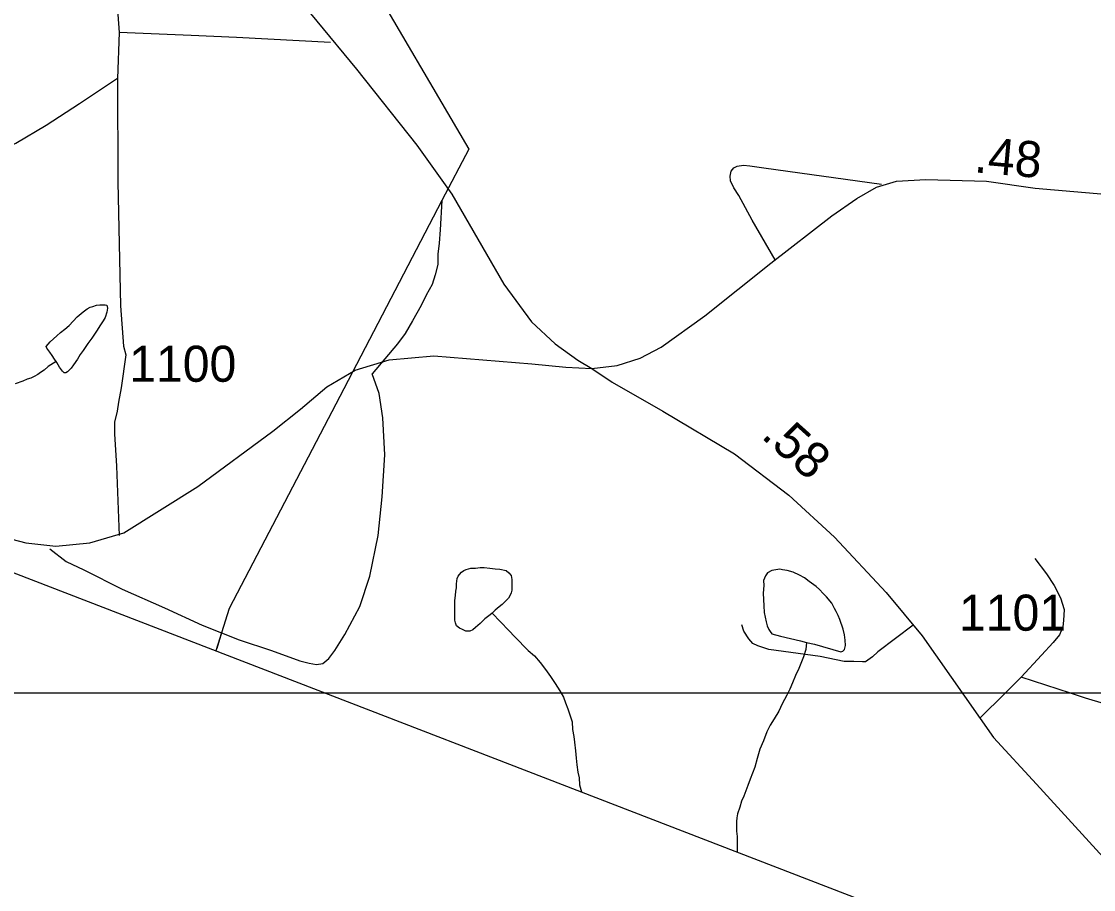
# Model space of a CAD drawing. Extents: x 2001466 to 2224147, y 644118 to 847247.
# Drawn here: x 2048097 to 2051817, y 657493 to 660503 of the extents above; entities that cross this region are included whole.
import ezdxf

# ---------------------------------------------------------------- set-up
doc = ezdxf.new("R2010")
doc.units = 0
for name, color, linetype in [('Exist Boundary Political CountyLine', 7, 'Continuous'), ('Exist Hydrographic Misc Water Feature', 7, 'Continuous'), ('Exist Road Non-System Type 51', 7, 'Continuous'), ('Exist Road Secondary Mileage Hundredths English Label', 7, 'Continuous'), ('Exist Road Secondary Type 51 Attributed', 7, 'Continuous'), ('Exist Road Secondary Type 51 Number Label', 7, 'Continuous'), ('Exist Utilities Electrical Transmission Line', 7, 'Continuous'), ('Map Preparation Inset Cut Line', 7, 'Continuous')]:
    doc.layers.add(name, color=color, linetype=linetype)

msp = doc.modelspace()

# ---------------------------------------------------------------- linework, layer by layer
at = {"layer": 'Exist Boundary Political CountyLine'}
msp.add_lwpolyline([(2025347, 667357.1), (2026293.9, 666990.5), (2073692.9, 648709.4), (2076162.7, 647794.5), (2078580.1, 646988.2), (2083338.8, 645254.9), (2086621.1, 644117.9)], dxfattribs=at)
at = {"layer": 'Exist Hydrographic Misc Water Feature'}
for points in [[(2048217.7, 659324.5), (2048211.7, 659332.5), (2048203.7, 659344.4), (2048195.5, 659356.4), (2048185.7, 659370.4), (2048183.6, 659376.4), (2048189.6, 659384.4), (2048197.6, 659392.4), (2048219.7, 659412.5), (2048233.5, 659424.5), (2048247.4, 659436.5), (2048263.4, 659448.5), (2048291.3, 659478.6), (2048311.4, 659496.6), (2048325.3, 659506.6), (2048335.4, 659512.7), (2048345.4, 659514.7), (2048357.3, 659518.7), (2048369.4, 659520.7), (2048381.3, 659520.7), (2048387.5, 659520.7), (2048393.4, 659518.7), (2048395.5, 659508.8), (2048393.4, 659494.8), (2048387.5, 659476.7), (2048381.3, 659464.7), (2048371.5, 659450.7), (2048357.5, 659428.7), (2048341.5, 659404.6), (2048327.6, 659386.7), (2048311.6, 659362.6), (2048301.6, 659348.6), (2048291.7, 659332.6), (2048277.8, 659312.6), (2048269.8, 659300.5), (2048257.7, 659288.5), (2048251.7, 659284.5), (2048245.8, 659284.5), (2048239.8, 659290.5), (2048229.8, 659304.5), (2048219.7, 659320.5), (2048217.7, 659324.5)], [(2048217.7, 659324.5), (2048189.8, 659306.4), (2048175.9, 659294.4), (2048163.8, 659286.3), (2048153.9, 659278.3), (2048141.8, 659272.3), (2048129.9, 659266.3), (2048117.8, 659262.3), (2048101.8, 659256.3), (2048075.8, 659246.2)], [(2049731.2, 658451.5), (2049723.2, 658445.5), (2049705.1, 658431.4), (2049689.1, 658415.4), (2049673.1, 658401.4), (2049663.3, 658393.4), (2049653.3, 658389.3), (2049639.3, 658389.3), (2049627.2, 658395.2), (2049617.2, 658399.2), (2049607.1, 658407.3), (2049603, 658417.3), (2049601.2, 658427.3), (2049601.2, 658439.3), (2049601.2, 658451.3), (2049601.2, 658459.3), (2049601, 658473.2), (2049601, 658495.2), (2049603, 658513.2), (2049605.1, 658527.2), (2049606.9, 658539.2), (2049606.9, 658553.2), (2049608.8, 658571.2), (2049612.9, 658579.2), (2049616.8, 658585.3), (2049624.8, 658593.3), (2049632.8, 658599.3), (2049640.7, 658603.2), (2049656.7, 658607.3), (2049672.7, 658607.3), (2049688.7, 658609.3), (2049702.7, 658609.3), (2049722.8, 658607.5), (2049740.8, 658605.5), (2049756.8, 658603.5), (2049778.7, 658599.5), (2049788.8, 658591.6), (2049796.8, 658581.6), (2049798.8, 658567.6), (2049798.8, 658551.6), (2049798.8, 658541.6), (2049798.8, 658531.6), (2049796.8, 658521.6), (2049792.9, 658513.5), (2049787, 658503.5), (2049776.9, 658493.5), (2049765, 658481.5), (2049755, 658473.5), (2049741, 658461.5), (2049731.2, 658451.5)], [(2050821, 658349.5), (2050848.9, 658343.6), (2050941, 658317.8), (2050947.1, 658319.8), (2050953.1, 658325.8), (2050957, 658339.8), (2050954.9, 658357.8), (2050952.9, 658375.8), (2050949, 658395.8), (2050936.9, 658429.7), (2050930.9, 658443.7), (2050924.8, 658457.7), (2050918.8, 658467.7), (2050908.8, 658485.7), (2050890.7, 658507.6), (2050882.8, 658515.6), (2050878.6, 658519.6), (2050866.8, 658533.6), (2050854.7, 658543.6), (2050830.7, 658561.5), (2050814.7, 658573.5), (2050796.6, 658583.5), (2050774.7, 658593.4), (2050754.6, 658599.4), (2050738.6, 658601.4), (2050728.6, 658603.4), (2050714.6, 658601.3), (2050700.7, 658599.3), (2050686.5, 658591.2), (2050678.5, 658581.2), (2050672.6, 658565.2), (2050672.8, 658547.2), (2050670.7, 658521.2), (2050672.8, 658477.2), (2050674.8, 658453.2), (2050681, 658421.3), (2050684.9, 658407.3), (2050691, 658395.3), (2050694.9, 658387.3), (2050700.9, 658379.3), (2050731, 658371.3), (2050800.9, 658355.5), (2050821, 658349.5)], [(2049731.2, 658451.5), (2049789, 658391.6), (2049809.3, 658369.6), (2049855.2, 658321.7), (2049877.4, 658303.8), (2049897.3, 658279.8), (2049915.3, 658255.8), (2049933.6, 658231.9), (2049949.6, 658208), (2049965.6, 658182), (2049977.7, 658160), (2049985.6, 658140), (2049993.6, 658120), (2049997.5, 658106), (2050007.8, 658074.1), (2050009.6, 658048.1), (2050013.7, 658024.1), (2050015.8, 658004.1), (2050019.9, 657974), (2050021.9, 657948.1), (2050024, 657926.1), (2050027.9, 657900.1), (2050032, 657880.1), (2050034, 657856.1), (2050038.1, 657840.1), (2050041, 657831.6)], [(2050821, 658349.5), (2050819.2, 658325.5), (2050811, 658299.5), (2050795.2, 658259.5), (2050783.3, 658235.5), (2050773.3, 658209.4), (2050763.4, 658187.5), (2050753.4, 658167.5), (2050737.4, 658137.4), (2050725.5, 658111.4), (2050709.5, 658085.4), (2050695.5, 658063.3), (2050683.6, 658039.4), (2050671.8, 658009.3), (2050659.7, 657979.3), (2050649.8, 657947.3), (2050641.8, 657917.3), (2050626, 657875.3), (2050618, 657853.3), (2050604.1, 657817.2), (2050596.1, 657799.2), (2050590.1, 657779.2), (2050582.1, 657755.2), (2050580.1, 657741.2), (2050578.2, 657729.2), (2050578.2, 657715.2), (2050578.2, 657695.2), (2050580.3, 657677.2), (2050580.3, 657649.2), (2050580.3, 657635.2), (2050580.4, 657623.6)]]:
    msp.add_lwpolyline(points, dxfattribs=at)
at = {"layer": 'Exist Road Non-System Type 51'}
for p, q in [((2048436.2, 660465), (2048431, 660305.1)), ((2051566.7, 658229.5), (2051510.2, 658173.9)), ((2051737.3, 658173.9), (2051566.7, 658229.5)), ((2051510.2, 658173.9), (2051422.7, 658087.7))]:
    msp.add_line(p, q, dxfattribs=at)
for points in [[(2048921.6, 660731.2), (2048505.6, 660731.6), (2048483.6, 660732.1), (2048467.7, 660734.4), (2048455.7, 660732.6), (2048443.6, 660730.9), (2048435.4, 660719.1), (2048428.9, 660697.2), (2048424.5, 660677.3), (2048423.7, 660637.3), (2048436.2, 660465)], [(2049169.5, 660430.1), (2048843.8, 660446.8), (2048686, 660454), (2048436.2, 660465)], [(2048431, 660305.1), (2048299.2, 660217.8), (2048183.6, 660142.2), (2048078.4, 660080.3), (2047999.8, 660049.9), (2047938.9, 660009.1), (2047874.2, 659974.4), (2047805.6, 659941.8), (2047741.1, 659919.1), (2047698.6, 659896)], [(2048431, 660305.1), (2048431.7, 659947.1), (2048440.9, 659516.9), (2048452.1, 659376.7), (2048459.4, 659346.6), (2048443.1, 659232.9), (2048434.1, 659183.1), (2048429.5, 659151.2), (2048420.7, 659113.3), (2048419.9, 659073.4), (2048427.6, 658961.2), (2048436.7, 658721)], [(2050712.4, 659676.4), (2050633, 659814.4), (2050586.7, 659899.4), (2050569.2, 659925.7), (2050557.7, 659950), (2050556, 659966), (2050560.4, 659983.9), (2050568.7, 659995.7), (2050580.8, 660001.5), (2050602.8, 660005), (2050624.8, 660002.6), (2050672.7, 659995.6), (2051081.8, 659938.8)], [(2049556.4, 659882.3), (2049550.3, 659780.4), (2049547.3, 659734.5), (2049542.6, 659696.6), (2049541.8, 659660.6), (2049533.1, 659624.8), (2049522.4, 659591), (2049501.6, 659553.4), (2049484.9, 659517.7), (2049453.8, 659464.4), (2049429, 659420.9), (2049402.2, 659385.4), (2049314.1, 659281.2)], [(2048791.7, 658382.8), (2048853.3, 658358.6), (2048964.6, 658322.3), (2049063.9, 658286.3), (2049095.7, 658277.6), (2049121.6, 658273.1), (2049143.7, 658276.7), (2049164, 658294.2), (2049184.6, 658321.8), (2049219.7, 658377.1), (2049271.7, 658474.1), (2049305.8, 658579.4), (2049334.7, 658720.8), (2049349.4, 658854.5), (2049358.4, 659000.3), (2049351, 659128.5), (2049338.7, 659212.7), (2049314.1, 659281.2)], [(2048195.7, 658673.9), (2048252.9, 658630.7), (2048314.3, 658601.5), (2048446.9, 658534.8), (2048593.6, 658469.8), (2048724.4, 658409.2), (2048791.7, 658382.8)], [(2051613.1, 658640.5), (2051654, 658587.7), (2051681.2, 658547.1), (2051702.3, 658504.7), (2051715.5, 658464.4), (2051712.7, 658426.5), (2051710.3, 658404.5), (2051699.7, 658376.8), (2051677.1, 658349.2), (2051636.3, 658306), (2051566.7, 658229.5)], [(2051191.1, 658410), (2051068.5, 658317.6), (2051050.1, 658299.9), (2051025.8, 658282.4), (2051015.8, 658282.6), (2050985.8, 658283.3), (2050951.8, 658283.9), (2050868.2, 658301.6), (2050690.6, 658325.2), (2050652.9, 658338), (2050635.1, 658346.4), (2050621.4, 658362.7), (2050603.9, 658389), (2050596.4, 658411.2)], [(2052440, 658089.7), (2052417.9, 658090.2), (2052387.6, 658078.8), (2052357.2, 658057.4), (2052344.9, 658041.7), (2052310.7, 658032.4), (2052296.4, 658020.6), (2052268.4, 658019.2), (2052230.6, 658030), (2052095.3, 658062.7), (2051932.3, 658114), (2051789.2, 658156.9), (2051737.3, 658173.9)]]:
    msp.add_lwpolyline(points, dxfattribs=at)
at = {"layer": 'Exist Road Secondary Type 51 Attributed'}
for points in [[(2047317.1, 662412), (2047529.3, 662218.6), (2048014.4, 661781.3), (2048220.7, 661592.2), (2048349.5, 661460.1), (2048474, 661313.3), (2048683.6, 661045), (2048847.2, 660838), (2049259.4, 660337.3), (2049468.9, 660074.3), (2049591.3, 659904.2), (2049771.3, 659592.6), (2049867.4, 659461.6), (2049949.2, 659385.6), (2050028.3, 659328.5), (2050076.9, 659300)], [(2050076.9, 659300), (2050164.5, 659309.5), (2050244.7, 659335.9), (2050317.6, 659374), (2050468.5, 659481.7), (2050697, 659664.4), (2050909.2, 659829.2), (2050995.8, 659889.4), (2051063.8, 659928.5), (2051133.5, 659949.6), (2051234.8, 659954.9), (2051446, 659949.6), (2051614.8, 659925.3), (2051923.6, 659897.9), (2052047.2, 659884.4)], [(2046185.3, 659508.1), (2046469.3, 659377.1), (2047052, 659116.2), (2047633, 658861.7), (2048014.6, 658721.2), (2048112.8, 658694.8), (2048217.3, 658683.1), (2048334.4, 658695.8), (2048452.7, 658729.6), (2048709.7, 658890.2), (2048969.4, 659082.4), (2049065.9, 659158.5), (2049156.7, 659236.6), (2049255.9, 659293.7), (2049373.1, 659329.6), (2049528.3, 659343.3), (2049868.7, 659315.9), (2049986.1, 659304.2), (2050076.9, 659300)], [(2050076.9, 659300), (2050146.6, 659252.5), (2050322.8, 659152.1), (2050571.4, 659004.3), (2050760.4, 658860.6), (2050918.2, 658714.8), (2051097.6, 658522.6), (2051222.2, 658372.6), (2051469.7, 658020.8), (2051619.6, 657858.2), (2051912.5, 657538.1), (2051997, 657415.6), (2052073.5, 657263.5), (2052123.1, 657140.9), (2052158.1, 657015.1)]]:
    msp.add_lwpolyline(points, dxfattribs=at)
at = {"layer": 'Exist Utilities Electrical Transmission Line'}
for p, q in [((2049556.4, 659882.3), (2049215.5, 659229)), ((2048791.7, 658382.8), (2048775, 658329.3))]:
    msp.add_line(p, q, dxfattribs=at)
for points in [[(2049431.9, 661724.6), (2049282.9, 660685.8), (2049649.2, 660060), (2049556.4, 659882.3)], [(2049215.5, 659229), (2048817.9, 658467.1), (2048772.4, 658320.9)]]:
    msp.add_lwpolyline(points, dxfattribs=at)
at = {"layer": 'Map Preparation Inset Cut Line'}
for p, q in [((2049569.8, 658173.9), (2049181, 658173.9)), ((2051319.6, 658173.9), (2049569.8, 658173.9)), ((2051510.2, 658173.9), (2051319.6, 658173.9)), ((2051737.3, 658173.9), (2051510.2, 658173.9)), ((2052441.3, 658173.9), (2051737.3, 658173.9))]:
    msp.add_line(p, q, dxfattribs=at)
msp.add_lwpolyline([(2049181, 658173.9), (2029908.9, 658173.9), (2029908.9, 665546.5)], dxfattribs=at)

# ---------------------------------------------------------------- texts
at = {"layer": 'Exist Road Secondary Mileage Hundredths English Label'}
for s, rotation, p in [('.48', 354.9185, (2051400.9, 659980.2)), ('.58', 318.1245, (2050660.4, 659061.8))]:
    msp.add_text(s, height=125, rotation=rotation, dxfattribs=at).set_placement(p)
at = {"layer": 'Exist Road Secondary Type 51 Number Label'}
for s, p in [('1100', (2048471.2, 659253.6)), ('1101', (2051350.2, 658390.6))]:
    msp.add_text(s, height=125, dxfattribs=at).set_placement(p)

doc.saveas('drawing.dxf')
